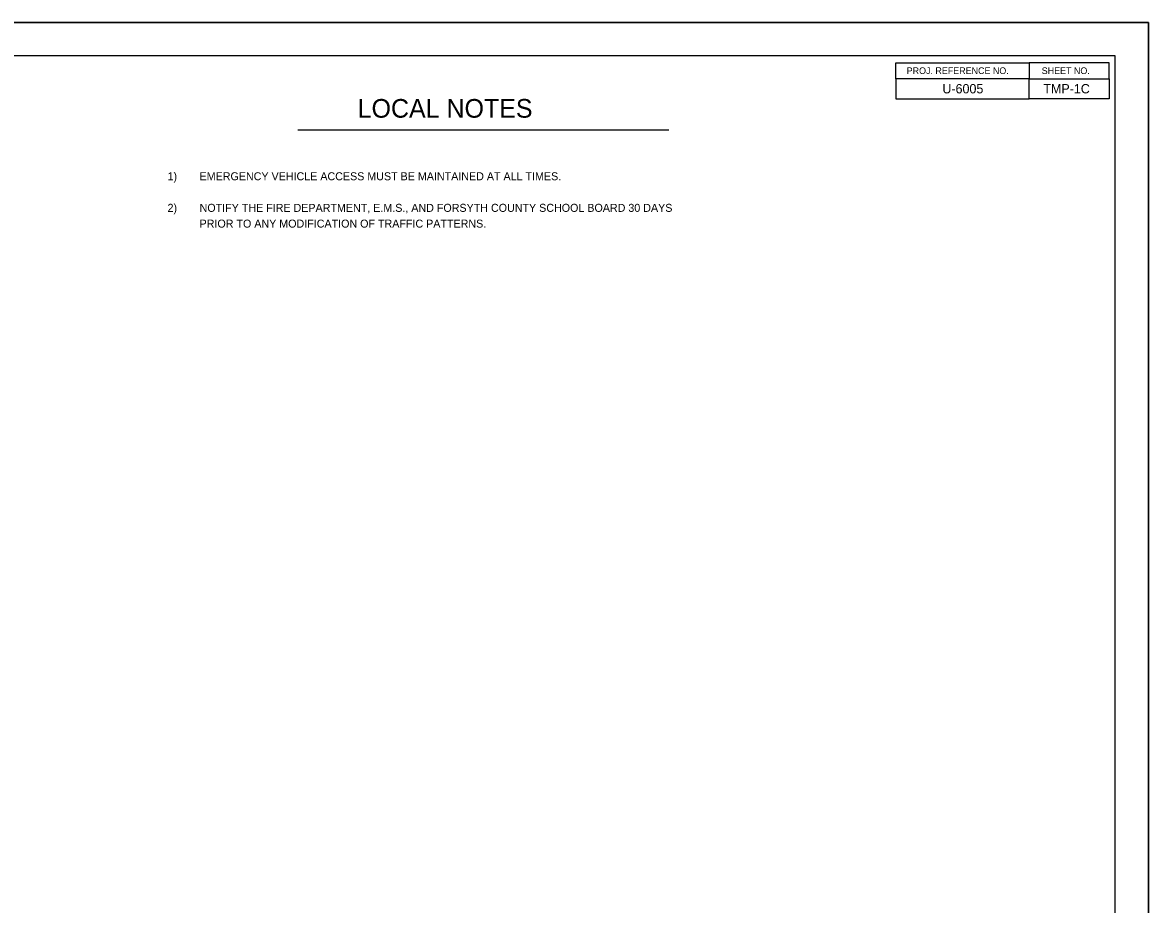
# Model space of a CAD drawing. Extents: x 762655 to 770567, y 650864 to 655190.
# Drawn here: x 765365 to 766209, y 653217 to 653879 of the extents above; entities that cross this region are included whole.
import ezdxf

# ---------------------------------------------------------------- set-up
doc = ezdxf.new("R2010")
doc.units = 0
for name, color, linetype in [('Default', 7, 'Continuous'), ('DEV BORDER CELL', 7, 'Continuous'), ('DEV TRANSPORTATION OPERATIONS PLAN SHEET', 7, 'Continuous'), ('Scratch_Level_3', 7, 'Continuous'), ('Sheet Plot Border Outside CELL', 7, 'Continuous')]:
    doc.layers.add(name, color=color, linetype=linetype)

msp = doc.modelspace()

# ---------------------------------------------------------------- linework, layer by layer
at = {"layer": 'DEV BORDER CELL'}
for p, q in [((766119.5, 653836.61), (766179.49, 653836.61)), ((765571.28, 653798.23), (765849.23, 653798.23))]:
    msp.add_line(p, q, dxfattribs=at)
for points in [[(766183.85, 653853.76), (764683.84, 653853.76), (764683.84, 652803.75), (766183.85, 652803.75)], [(766019.49, 653848.61), (766119.5, 653848.61), (766119.5, 653836.61), (766019.49, 653836.61)], [(766119.5, 653836.61), (766179.49, 653836.61), (766179.49, 653848.62), (766119.5, 653848.62)], [(766119.5, 653836.61), (766019.49, 653836.61), (766019.49, 653821.62), (766119.5, 653821.62)], [(766119.5, 653836.61), (766179.49, 653836.61), (766179.49, 653821.62), (766119.5, 653821.62)]]:
    msp.add_lwpolyline(points, close=True, dxfattribs=at)
at = {"layer": 'Scratch_Level_3'}
msp.add_lwpolyline([(764520.84, 653878.75), (766208.85, 653878.75), (766208.85, 652778.75), (764520.84, 652778.75)], close=True, dxfattribs=at)
at = {"layer": 'Sheet Plot Border Outside CELL'}
msp.add_lwpolyline([(764520.85, 652778.75), (766208.85, 652778.75), (766208.85, 653878.75), (764520.85, 653878.75)], close=True, dxfattribs=at)

# ---------------------------------------------------------------- texts
at = {"layer": 'Default'}
for s, p in [('1)', (765473.57, 653760.47)), ('EMERGENCY VEHICLE ACCESS MUST BE MAINTAINED AT ALL TIMES.', (765497.57, 653760.47)), ('2)', (765473.57, 653736.8)), ('NOTIFY THE FIRE DEPARTMENT, E.M.S., AND FORSYTH COUNTY SCHOOL BOARD 30 DAYS ', (765497.57, 653736.8)), ('PRIOR TO ANY MODIFICATION OF TRAFFIC PATTERNS.', (765497.57, 653724.97))]:
    msp.add_text(s, height=6, dxfattribs=at).set_placement(p)
at = {"layer": 'DEV BORDER CELL'}
for s, height, p in [('PROJ. REFERENCE NO.', 4.9992, (766027.6, 653840.11)), ('SHEET NO.', 4.999, (766128.83, 653840.11))]:
    msp.add_text(s, height=height, rotation=0.00056, dxfattribs=at).set_placement(p)
for s, p in [('U-6005', (766054.36, 653825.61)), ('TMP-1C', (766130.03, 653825.61))]:
    msp.add_text(s, height=7, dxfattribs=at).set_placement(p)
at = {"layer": 'DEV TRANSPORTATION OPERATIONS PLAN SHEET'}
msp.add_text('LOCAL NOTES ', height=14, dxfattribs=at).set_placement((765616.06, 653807.39))

doc.saveas('drawing.dxf')
